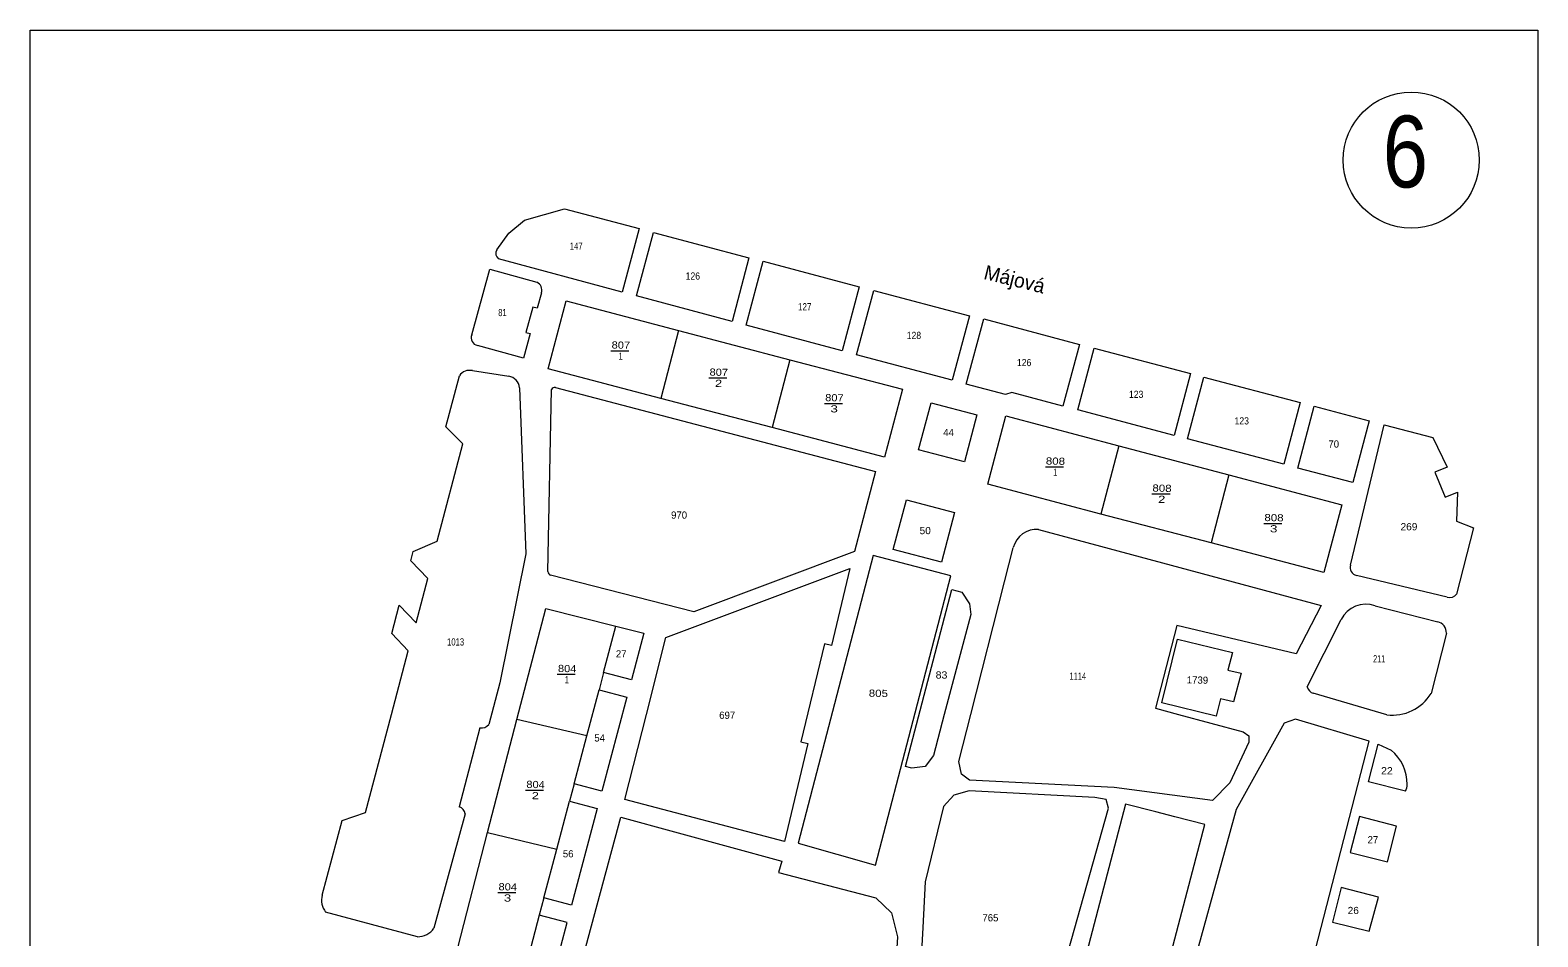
# Model space of a CAD drawing. Extents: x -843471 to -843261, y -1003203 to -1002905.
# Drawn here: x -843471 to -843261, y -1003031 to -1002904.7 of the extents above; entities that cross this region are included whole.
import ezdxf
from ezdxf.enums import TextEntityAlignment as Align

# ---------------------------------------------------------------- set-up
doc = ezdxf.new("R2010")
doc.units = 0
doc.header["$LTSCALE"] = 0.4
doc.layers.add('20', color=7, linetype='Continuous')
for name, color, linetype, lineweight in [('35', 7, 'Continuous', 13), ('38', 7, 'Continuous', 13), ('43', 7, 'Continuous', 13), ('44', 7, 'Continuous', 13)]:
    doc.layers.add(name, color=color, linetype=linetype, lineweight=lineweight)

msp = doc.modelspace()

# ---------------------------------------------------------------- linework, layer by layer
at = {"layer": '35'}
for p, q in [((-843390.09, -1002949.335), (-843387.576, -1002949.335)), ((-843376.449, -1002953.116), (-843373.935, -1002953.116)), ((-843360.343, -1002956.667), (-843357.829, -1002956.667)), ((-843329.557, -1002965.497), (-843327.043, -1002965.497)), ((-843314.715, -1002969.269), (-843312.201, -1002969.269)), ((-843299.119, -1002973.376), (-843296.605, -1002973.376)), ((-843397.565, -1002994.399), (-843395.051, -1002994.399)), ((-843401.968, -1003010.548), (-843399.454, -1003010.548)), ((-843405.842, -1003024.807), (-843403.328, -1003024.807))]:
    msp.add_line(p, q, dxfattribs=at)
at = {"layer": '38'}
for p, q in [((-843380.64, -1002946.5), (-843383.13, -1002955.97)), ((-843365.14, -1002950.57), (-843367.63, -1002960.04)), ((-843319.33, -1002962.57), (-843321.83, -1002972.07)), ((-843303.99, -1002966.63), (-843306.48, -1002976.1)), ((-843391.085, -1002994.132), (-843391.725, -1002996.548)), ((-843393.43, -1003002.98), (-843403.17, -1003000.7)), ((-843395.195, -1003009.652), (-843395.835, -1003012.068)), ((-843407.25, -1003016.45), (-843397.6, -1003018.74)), ((-843399.404, -1003025.537), (-843400.046, -1003027.953))]:
    msp.add_line(p, q, dxfattribs=at)
for points in [[(-843396.32, -1002942.39), (-843380.64, -1002946.5), (-843365.14, -1002950.57), (-843349.48, -1002954.68), (-843351.96, -1002964.15), (-843367.63, -1002960.04), (-843383.13, -1002955.97), (-843398.81, -1002951.86)], [(-843335.06, -1002958.41), (-843319.33, -1002962.57), (-843303.99, -1002966.63), (-843288.28, -1002970.78), (-843290.76, -1002980.22), (-843306.48, -1002976.1), (-843321.83, -1002972.07), (-843337.56, -1002967.93)], [(-843353.55, -1002977.83), (-843364, -1003017.94), (-843353.23, -1003020.97), (-843342.72, -1002980.68)], [(-843311.18, -1002989.49), (-843303.5, -1002991.36), (-843304.13, -1002993.82), (-843302.31, -1002994.26), (-843303.36, -1002998.23), (-843305.19, -1002997.8), (-843305.77, -1003000.22), (-843313.34, -1002998.38)], [(-843328.45, -1003050.8), (-843317.44, -1003053.71), (-843307.34, -1003015.31), (-843311.55, -1003014.24), (-843314.18, -1003013.56), (-843318.38, -1003012.49)]]:
    msp.add_lwpolyline(points, close=True, dxfattribs=at)
msp.add_lwpolyline([(-843401.85, -1003034.75), (-843411.41, -1003032.51), (-843407.25, -1003016.45), (-843403.17, -1003000.7), (-843399.16, -1002985.21), (-843389.38, -1002987.7)], dxfattribs=at)
at = {"layer": '43'}
for p, q in [((-843409.469, -1002947.111), (-843406.96, -1002937.98)), ((-843406.96, -1002937.98), (-843400.386, -1002939.786)), ((-843409.37, -1002952.1), (-843404.31, -1002952.88)), ((-843398.86, -1002980.1), (-843398.34, -1002954.74)), ((-843287.05, -1002979.18), (-843282.376, -1002959.637)), ((-843335.25, -1002981.52), (-843334.028, -1002976.758)), ((-843378.546, -1002985.677), (-843398.49, -1002980.599)), ((-843273.58, -1002983.64), (-843286.24, -1002980.63)), ((-843283.63, -1002984.84), (-843274.92, -1002987.07)), ((-843293.09, -1002996.16), (-843288.36, -1002986.78)), ((-843273.71, -1002988.68), (-843275.83, -1002997.08)), ((-843282.01, -1003000.04), (-843292.25, -1002997.05)), ((-843408.314, -1003001.856), (-843411.21, -1003012.86)), ((-843410.367, -1003013.852), (-843414.73, -1003029.75)), ((-843365.92, -1003017.67), (-843366.042, -1003017.638)), ((-843417.03, -1003030.97), (-843429.809, -1003027.536))]:
    msp.add_line(p, q, dxfattribs=at)
for points in [[(-843405.97, -1002935.27), (-843404.296, -1002932.955), (-843402.13, -1002931.158), (-843396.54, -1002929.54), (-843386.16, -1002932.304), (-843388.518, -1002941.159), (-843405.71, -1002936.51)], [(-843399.76, -1002941.24), (-843400.354, -1002943.403), (-843400.95, -1002943.239), (-843401.92, -1002946.77), (-843401.324, -1002946.934), (-843402.269, -1002950.371), (-843408.68, -1002948.61)], [(-843415.56, -1002981.05), (-843417.966, -1002978.596), (-843417.633, -1002977.313), (-843414.28, -1002975.87), (-843410.7, -1002962.29), (-843413.059, -1002959.944), (-843411.18, -1002952.81)], [(-843402.8, -1002954.47), (-843401.93, -1002977.61), (-843405.56, -1002995.59), (-843407.091, -1003001.408)], [(-843397.805, -1002954.452), (-843353.242, -1002966.141), (-843356.17, -1002977.313), (-843378.546, -1002985.677)], [(-843282.376, -1002959.637), (-843275.58, -1002961.43), (-843273.591, -1002965.538), (-843275.3, -1002966.24), (-843273.87, -1002969.72), (-843272.161, -1002969.018), (-843272.28, -1002973.08), (-843269.91, -1002973.99), (-843272.28, -1002983.22)], [(-843330.502, -1002974.214), (-843292.355, -1002984.505), (-843291.15, -1002984.83), (-843294.65, -1002991.53), (-843311.26, -1002987.611), (-843314.21, -1002999.13), (-843310.996, -1003000), (-843302.02, -1003002.43), (-843301.21, -1003002.95), (-843301.23, -1003003.84), (-843303.87, -1003009.51), (-843306.26, -1003012), (-843319.96, -1003010.152), (-843340.14, -1003009.14), (-843341.26, -1003008.29), (-843341.62, -1003006.56), (-843339.951, -1003000), (-843335.25, -1002981.52)], [(-843430.29, -1003025.17), (-843427.502, -1003014.744), (-843424.27, -1003013.67), (-843420.658, -1003000), (-843418.32, -1002991.15), (-843420.568, -1002988.729), (-843419.553, -1002984.774), (-843417.22, -1002987.21), (-843415.56, -1002981.05)], [(-843279.386, -1003010.662), (-843284.54, -1003009.4), (-843283.212, -1003004.109), (-843281.41, -1003004.97)], [(-843330.68, -1003048.19), (-843320.79, -1003013.05), (-843321.09, -1003011.86), (-843322.66, -1003011.55), (-843340.18, -1003010.64), (-843342.33, -1003011.23), (-843343.75, -1003012.82), (-843346.29, -1003023.32), (-843346.64, -1003029.65), (-843347.37, -1003043.16)]]:
    msp.add_lwpolyline(points, dxfattribs=at)
for points in [[(-843386.505, -1002941.695), (-843384.147, -1002932.84), (-843370.85, -1002936.38), (-843373.208, -1002945.236)], [(-843368.849, -1002936.866), (-843355.494, -1002940.438), (-843357.874, -1002949.337), (-843371.229, -1002945.765)], [(-843353.47, -1002940.91), (-843340.151, -1002944.472), (-843342.548, -1002953.436), (-843355.867, -1002949.873)], [(-843338.14, -1002944.876), (-843324.822, -1002948.438), (-843327.12, -1002957.03), (-843334.224, -1002955.13), (-843335.13, -1002955.42), (-843340.571, -1002953.965)], [(-843325.047, -1002957.577), (-843322.778, -1002948.978), (-843309.363, -1002952.517), (-843311.632, -1002961.116)], [(-843307.498, -1002953.009), (-843294.094, -1002956.545), (-843296.363, -1002965.145), (-843309.766, -1002961.608)], [(-843345.45, -1002956.59), (-843339.12, -1002958.26), (-843340.84, -1002964.79), (-843347.21, -1002963.12)], [(-843292.116, -1002957.067), (-843284.455, -1002959.089), (-843286.724, -1002967.688), (-843294.385, -1002965.667)], [(-843350.751, -1002977.016), (-843348.924, -1002970.076), (-843342.223, -1002971.839), (-843344.049, -1002978.779)], [(-843363.621, -1003003.824), (-843362.649, -1003004.058), (-843365.92, -1003017.67), (-843388.14, -1003011.86), (-843385.138, -1003000), (-843382.42, -1002989.26), (-843356.79, -1002979.68), (-843359.36, -1002990.375), (-843360.333, -1002990.142)], [(-843342.599, -1002982.588), (-843341.18, -1002982.96), (-843340.14, -1002984.57), (-843339.95, -1002986.07), (-843343.647, -1003000), (-843345.16, -1003005.7), (-843346.3, -1003007.23), (-843348.16, -1003007.46), (-843348.365, -1003007.406), (-843349.049, -1003007.227)], [(-843389.38, -1002987.7), (-843385.504, -1002988.687), (-843387.219, -1002995.156), (-843391.085, -1002994.132)], [(-843391.725, -1002996.548), (-843387.859, -1002997.573), (-843391.332, -1003010.674), (-843395.195, -1003009.652), (-843393.43, -1003002.98)], [(-843284.45, -1003003.7), (-843294.7, -1003000.64), (-843296.31, -1003001.22), (-843302.99, -1003013.24), (-843302.99, -1003013.24), (-843310.734, -1003041.383), (-843308.91, -1003041.72), (-843314.3, -1003061.74), (-843313.983, -1003062.586), (-843313.47, -1003062.92), (-843300.63, -1003066.44)], [(-843397.6, -1003018.74), (-843395.835, -1003012.068), (-843391.972, -1003013.09), (-843395.543, -1003026.562), (-843399.404, -1003025.537)], [(-843388.71, -1003014.29), (-843366.28, -1003020.43), (-843366.73, -1003022), (-843353.17, -1003025.55), (-843351, -1003027.64), (-843350.16, -1003030.95), (-843351.05, -1003045.19), (-843351.48, -1003049.64), (-843354.64, -1003061.08), (-843355.93, -1003064.18), (-843358.81, -1003068.24), (-843365.03, -1003077.8), (-843366.86, -1003079.21), (-843369.37, -1003079.38), (-843382.26, -1003076.4), (-843383.48, -1003078.02), (-843404.56, -1003073.14)], [(-843280.654, -1003015.558), (-843285.81, -1003014.22), (-843287.09, -1003019.24), (-843281.93, -1003020.54)], [(-843289.59, -1003028.91), (-843284.44, -1003030.17), (-843283.18, -1003025.43), (-843288.35, -1003024.1)], [(-843401.85, -1003034.75), (-843397.955, -1003035.663), (-843396.184, -1003028.978), (-843400.046, -1003027.953)]]:
    msp.add_lwpolyline(points, close=True, dxfattribs=at)
for centre, radius, start, end in [((-843405.1951, -1002935.7548), 0.9141, 147.9707, 235.71345), ((-843400.8665, -1002940.8546), 1.1717, 340.79692, 65.79554), ((-843408.3728, -1002947.4916), 1.1599, 160.86241, 254.63899), ((-843409.7638, -1002953.7581), 1.7042, 76.63844, 146.19825), ((-843404.583, -1002954.6513), 1.7922, 5.80664, 81.23682), ((-843397.8749, -1002954.9638), 0.5161, 82.17547, 154.30589), ((-843330.7387, -1002977.6014), 3.3961, 85.99432, 165.61324), ((-843398.2494, -1002980.0342), 0.6141, 186.15469, 246.92707), ((-843285.9792, -1002979.5331), 1.1275, 161.7514, 256.62586), ((-843284.8767, -1002988.5365), 3.9011, 71.36196, 153.23982), ((-843273.2314, -1002982.4971), 1.1949, 253.03687, 322.77203), ((-843275.3194, -1002988.6298), 1.6101, 358.21441, 75.63918), ((-843291.9109, -1002995.8885), 1.21, 192.96642, 253.72261), ((-843281.236, -1002993.7245), 6.3628, 263.01332, 328.1722), ((-843408.0753, -1003000.6144), 1.264, 259.13151, 321.13421), ((-843285.2311, -1003009.6757), 6.0617, 359.2027, 50.92273), ((-843281.2866, -1003009.7305), 2.1168, 333.90341, 359.2027), ((-843411.6136, -1003014.0578), 1.264, 9.37421, 71.37691), ((-843427.6721, -1003025.87), 2.7099, 165.02912, 217.93377), ((-843417.0506, -1003028.1531), 2.817, 270.41968, 325.46639)]:
    msp.add_arc(centre, radius, start, end, dxfattribs=at)
at = {"layer": '44'}
msp.add_lwpolyline([(-843470.967, -1002904.664), (-843260.967, -1002904.664), (-843260.967, -1003202.664), (-843470.967, -1003202.664)], close=True, dxfattribs=at)
msp.add_circle((-843278.5961, -1002922.7617), 9.4766, dxfattribs=at)

# ---------------------------------------------------------------- texts
at = {"layer": '20'}
msp.add_text('Májová', height=2, rotation=346.137, dxfattribs=at).set_placement((-843338.27, -1002939.302))
at = {"layer": '35'}
for s, width, p in [('807', 1.15, (-843388.702, -1002949.0385)), ('1', 0.7, (-843388.736, -1002950.5879)), ('807', 1.15, (-843375.061, -1002952.8185)), ('2', 1.35, (-843375.095, -1002954.3683)), ('807', 1.15, (-843358.955, -1002956.3695)), ('3', 1.4, (-843358.9895, -1002957.9195)), ('808', 1.2, (-843328.169, -1002965.2002)), ('1', 0.7, (-843328.2035, -1002966.7498)), ('808', 1.2, (-843313.327, -1002968.9722)), ('2', 1.35, (-843313.361, -1002970.5213)), ('808', 1.2, (-843297.7295, -1002973.0793)), ('3', 1.4, (-843297.7655, -1002974.6285)), ('804', 1.15, (-843396.177, -1002994.102)), ('1', 0.7, (-843396.2125, -1002995.6518)), ('805', 1.2, (-843352.8325, -1002997.5456)), ('804', 1.15, (-843400.5805, -1003010.25)), ('2', 1.35, (-843400.614, -1003011.8003)), ('804', 1.15, (-843404.454, -1003024.51)), ('3', 1.4, (-843404.4885, -1003026.0595))]:
    msp.add_text(s, height=1, rotation=358.734, dxfattribs=dict(at, width=width)).set_placement(p, align=Align.CENTER)
msp.add_text('1739', height=1, rotation=358.734, dxfattribs=at).set_placement((-843308.387, -1002995.6953), align=Align.CENTER)
at = {"layer": '43'}
for s, width, p in [('147', 0.8, (-843395.802, -1002935.252)), ('126', 0.9, (-843379.67, -1002939.419)), ('127', 0.85, (-843364.032, -1002943.697)), ('81', 0.75, (-843405.764, -1002944.502)), ('128', 0.9, (-843348.874, -1002947.688)), ('126', 0.9, (-843333.523, -1002951.47)), ('123', 0.9, (-843317.921, -1002955.9)), ('123', 0.9, (-843303.212, -1002959.593)), ('50', 1.05, (-843347.076, -1002974.878)), ('269', 1.05, (-843280.088, -1002974.339)), ('1013', 0.8, (-843412.902, -1002990.389)), ('211', 0.7, (-843283.91, -1002992.736)), ('83', 1.1, (-843344.845, -1002994.994)), ('1114', 0.65, (-843326.203, -1002995.16)), ('22', 1.1, (-843282.807, -1003008.333)), ('26', 1.05, (-843287.455, -1003027.796))]:
    msp.add_text(s, height=1, dxfattribs=dict(at, width=width)).set_placement(p)
for s, p in [('44', (-843343.785, -1002961.207)), ('70', (-843290.142, -1002962.816)), ('970', (-843381.694, -1002972.714)), ('27', (-843389.386, -1002992.054)), ('697', (-843374.992, -1003000.601)), ('54', (-843392.388, -1003003.761)), ('27', (-843284.679, -1003017.942)), ('56', (-843396.77, -1003019.903)), ('765', (-843338.332, -1003028.817))]:
    msp.add_text(s, height=1, dxfattribs=at).set_placement(p)
at = {"layer": '44', "width": 0.85}
msp.add_text('6', height=10, dxfattribs=at).set_placement((-843282.577, -1002926.576))

doc.saveas('drawing.dxf')
